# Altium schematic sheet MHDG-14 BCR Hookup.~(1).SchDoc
size B; Organization: Monterey Bay Aquarium Research Institute; Address1: 7700 Sandholdt Rd; Address2: Moss Landing, CA 95039-9644; CompanyName: MBARI
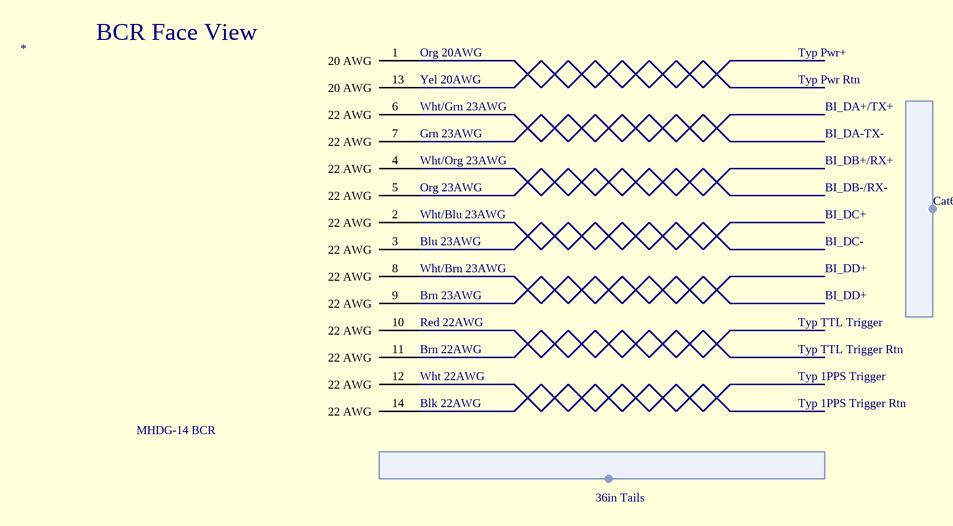
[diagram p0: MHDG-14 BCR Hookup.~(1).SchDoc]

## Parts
*  MHDG-14 BCR

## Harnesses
Cat6E wired to TIA/EIA 568A Standard: 
36in Tails: 

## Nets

Not connected (* = marked no-connect by the designer): * 1(20_AWG) 2(22_AWG) 3(22_AWG) 4(22_AWG) 5(22_AWG) 6(22_AWG) 7(22_AWG) 8(22_AWG) 9(22_AWG) 10(22_AWG) 11(22_AWG) 12(22_AWG) 13(20_AWG) 14(22_AWG)

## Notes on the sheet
- BCR Face View
- (near *) Org 20AWG
- (near *) Yel 20AWG
- (near *) Wht/Grn 23AWG
- Typ Pwr+
- Typ Pwr Rtn
- BI_DA+/TX+
- (near *) Grn 23AWG
- (near *) Wht/Org 23AWG
- BI_DA-TX-
- BI_DB+/RX+
- (near *) Org 23AWG
- (near *) Wht/Blu 23AWG
- (near *) Blu 23AWG
- BI_DB-/RX-
- BI_DC+
- BI_DC-
- (near *) Wht/Brn 23AWG
- (near *) Brn 23AWG
- BI_DD+
- (near *) Red 22AWG
- (near *) Brn 22AWG
- (near *) Wht 22AWG
- Typ TTL Trigger
- Typ TTL Trigger Rtn
- Typ 1PPS Trigger
- (near *) Blk 22AWG
- Typ 1PPS Trigger Rtn

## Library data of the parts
* = MHDG-14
